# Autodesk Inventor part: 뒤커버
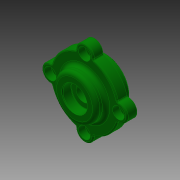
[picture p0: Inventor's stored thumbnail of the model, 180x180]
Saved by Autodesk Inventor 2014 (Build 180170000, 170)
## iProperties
Created: 2016-05
Part Number: 뒤커버
Document SubType Name: Modeling
Designer: mduedu
Density: 2.71 g/cm^3
Material: 알루미늄 6061
Appearance: Dark Green
Author: mduedu
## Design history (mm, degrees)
sketch "스케치1"
  geometry: C1 r 20 at (0, 0); C2 r 27.5 at (0, 0); 1 further point
  constraints: 2 centre point, 2 coincident
  dimensions: "d33" = 55 diameter of C2; "d34" = 40 diameter of C1
extrude "돌출1" new body sketch "스케치1" distance "d0" = 8; taper "d1" = 0 deg
extrude "돌출2" join sketch "스케치1" distance "d2" = 8; taper "d3" = 0 deg; dims "d35" = 9, "d36" = 0
sketch "스케치6"
  geometry: C1 r 17.5 at (0, 0); 2 further points
  constraints: 2 coincident, 1 centre point
  dimensions: "d42" = 35 diameter of C1
extrude "돌출4" join sketch "스케치6" distance "d43" = 8; taper "d44" = 0 deg
sketch "스케치4"
  geometry: L1 (0, -9)-(0, 16); L2 (-15, -9)-(-15, 0); L3 (-15, 0)-(-10, 0); L4 (-10, 0)-(-10, 3); L5 (-10, 3)-(-6, 3); L6 (-6, 3)-(-6, 8.7); L7 (-6, 8.7)-(-10, 8.7); L8 (-10, 8.7)-(-10, 16); L9 (20, -9)-(-20, -9) reference; L10 (17.5, 16)-(-17.5, 16) reference; 1 further point
  constraints: 16 end point, 6 parallel, 3 point on line, 2 midpoint, 2 perpendicular, 1 vertical
  dimensions: "d15" = 30 diameter of L2 L1; "d16" = 20 diameter of L8 L1; "d18" = 9 distance of L2.start L2.end; "d19" = 3 distance of L3.end L4.end; "d20" = 20 diameter of L4 L1; "d21" = 12 diameter of L6 L1; "d45" = 7.3 distance of L7.end L8.end
revolve "회전1" sketch "스케치4" stored, may be unused: angle "d22" = 90 deg
fillet "모깎기2" dims "d23" = 3
fillet "모깎기3" dims "d24" = 0.3
chamfer "모따기2" distance "d46" = 1; stored, may be unused: second distance "d47" = 2, angle "d48" = 45 deg
sketch "스케치7"
  geometry: C1 r 7 at (0, 27.5); 2 further points
  constraints: 3 vertical alignment, 1 centre point, 2 other
  dimensions: "d54" = 14 diameter of C1
extrude "돌출5" join sketch "스케치7" stored distance "d55" = 10; taper "d56" = 0 deg
fillet "모깎기6" dims "d57" = 1
sketch "스케치10"
  geometry: C1 r 17.5 at (0, 0) reference; A1 r 27.5 centre (0, 0) between (26.395, 7.718) and (7.718, 26.395) reference; A2 r 1 centre (7.999, 27.355) between (6.999, 27.373) and (7.718, 26.395) reference; A3 r 7 centre (0, 27.5) between (6.999, 27.373) and (-6.999, 27.373) reference; A4 r 1 centre (-7.999, 27.355) between (-7.718, 26.395) and (-6.999, 27.373) reference; A5 r 27.5 centre (0, 0) between (-7.718, 26.395) and (-26.395, 7.718) reference; A6 r 1 centre (-27.355, 7.999) between (-27.373, 6.999) and (-26.395, 7.718) reference; A7 r 7 centre (-27.5, 0) between (-27.373, 6.999) and (-27.373, -6.999) reference; A8 r 1 centre (-27.355, -7.999) between (-26.395, -7.718) and (-27.373, -6.999) reference; A9 r 27.5 centre (0, 0) between (-26.395, -7.718) and (-7.718, -26.395) reference; A10 r 1 centre (-7.999, -27.355) between (-6.999, -27.373) and (-7.718, -26.395) reference; A11 r 7 centre (0, -27.5) between (-6.999, -27.373) and (6.999, -27.373) reference; A12 r 1 centre (7.999, -27.355) between (7.718, -26.395) and (6.999, -27.373) reference; A13 r 27.5 centre (0, 0) between (7.718, -26.395) and (26.395, -7.718) reference; A14 r 1 centre (27.355, -7.999) between (27.373, -6.999) and (26.395, -7.718) reference; A15 r 7 centre (27.5, 0) between (27.373, -6.999) and (27.373, 6.999) reference; A16 r 1 centre (27.355, 7.999) between (26.395, 7.718) and (27.373, 6.999) reference; 4 further points
  constraints: 3 coincident
hole "구멍3" sketch "스케치10" at (0, 27.5), (-27.5, 0), (0, -27.5), (27.5, 0) diameter "d81" = 5.5; stored, may be unused: countersink angle "d85" = 90 deg, drill point angle "d87" = 118 deg; dims "d82" = 6, "d83" = 9.5, "d84" = 5.4, "d86" = 8
fillet "모깎기7" dims "d61" = 1
fillet "모깎기8" dims "d88" = 3
chamfer "모따기3" distance "d76" = 0.7; stored, may be unused: second distance "d77" = 2, angle "d78" = 30 deg
node "솔리드1"
pattern_circular "원형 패턴1" dims angle "d59" = 360 deg
node "투영된 루프1"
